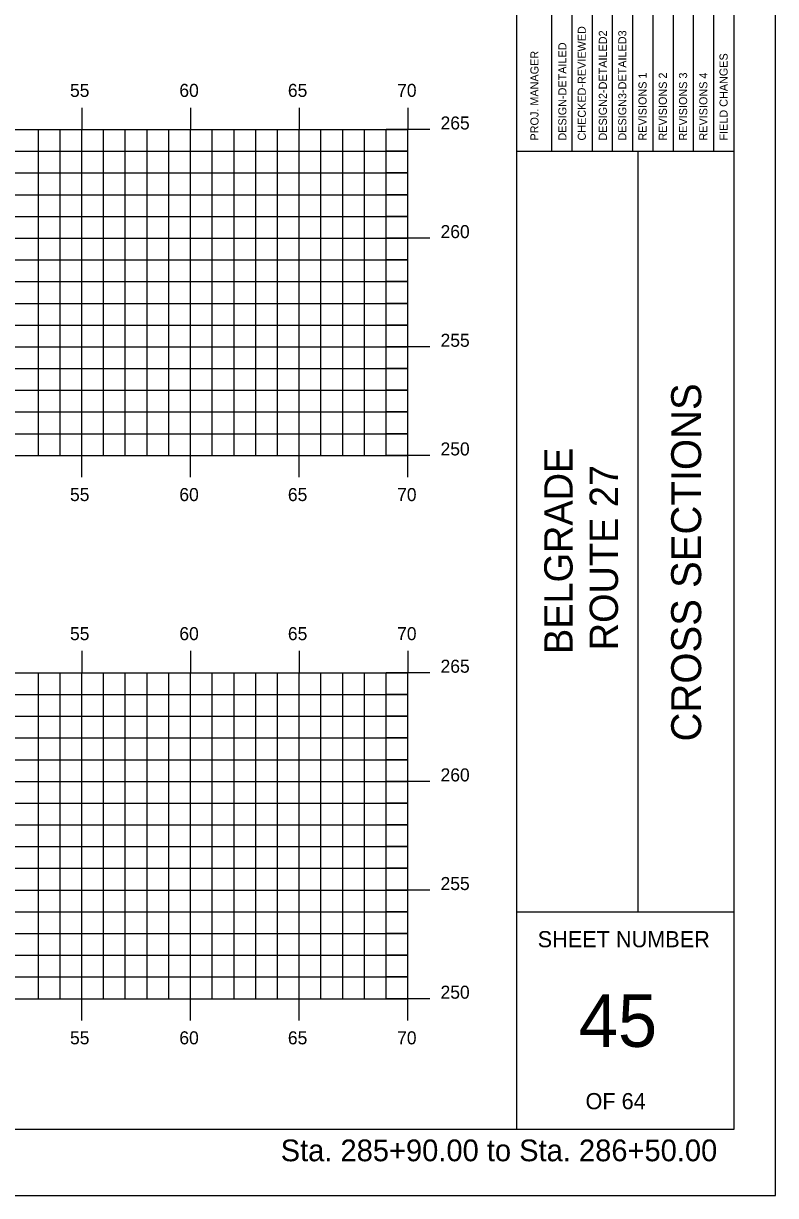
# Model space of a CAD drawing. Extents: x 856903 to 857073, y 366268 to 366378.
# Drawn here: x 857038.1 to 857072.7, y 366268.2 to 366322.1 of the extents above; entities that cross this region are included whole.
import ezdxf

# ---------------------------------------------------------------- set-up
doc = ezdxf.new("R2010")
doc.units = 0
for name, color, linetype in [('BORDER', 7, 'Continuous'), ('H_V ANNOTATION', 7, 'Continuous'), ('HIGHWAY_TITLE', 7, 'Continuous'), ('MAJOR', 7, 'Continuous'), ('MINOR', 7, 'Continuous'), ('PLOT BOUNDARY', 7, 'Continuous')]:
    doc.layers.add(name, color=color, linetype=linetype)

msp = doc.modelspace()

# ---------------------------------------------------------------- linework, layer by layer
at = {"layer": 'BORDER'}
for p, q in [((857060.784, 366271.236), (857060.784, 366376.239)), ((857070.784, 366271.236), (857070.784, 366376.236)), ((857060.784, 366316.239), (857070.784, 366316.239)), ((857066.375, 366281.239), (857066.375, 366316.239)), ((857060.784, 366281.239), (857070.784, 366281.239)), ((856910.784, 366271.236), (857070.784, 366271.236))]:
    msp.add_line(p, q, dxfattribs=at)
for points in [[(857063.332, 366316.242), (857063.332, 366333.739)], [(857064.263, 366333.739), (857064.263, 366316.242)], [(857065.195, 366316.242), (857065.195, 366333.739)], [(857066.127, 366316.242), (857066.127, 366333.739)], [(857067.058, 366316.242), (857067.058, 366333.739)], [(857067.99, 366316.242), (857067.99, 366333.739)], [(857068.922, 366316.242), (857068.922, 366333.739)], [(857069.853, 366316.242), (857069.853, 366333.739)], [(857062.4, 366316.242), (857062.4, 366333.033)]]:
    msp.add_lwpolyline(points, dxfattribs=at)
at = {"layer": 'MAJOR'}
for p, q in [((857040.784, 366318.238), (857040.784, 366317.236)), ((857045.784, 366318.238), (857045.784, 366317.236)), ((857050.784, 366318.238), (857050.784, 366317.236)), ((857055.784, 366318.238), (857055.784, 366317.236)), ((856915.784, 366317.236), (857055.784, 366317.236)), ((856915.784, 366317.236), (857055.784, 366317.236)), ((857040.784, 366302.236), (857040.784, 366317.236)), ((857045.784, 366302.236), (857045.784, 366317.236)), ((857050.784, 366302.236), (857050.784, 366317.236)), ((857056.786, 366317.236), (857054.782, 366317.236)), ((857055.784, 366302.236), (857055.784, 366317.236)), ((857055.784, 366302.236), (857055.784, 366317.236)), ((856915.784, 366312.236), (857055.784, 366312.236)), ((857056.786, 366312.236), (857054.782, 366312.236)), ((856915.784, 366307.236), (857055.784, 366307.236)), ((857056.786, 366307.236), (857054.782, 366307.236)), ((856915.784, 366302.236), (857055.784, 366302.236)), ((856915.784, 366302.236), (857055.784, 366302.236)), ((857040.784, 366301.234), (857040.784, 366302.236)), ((857045.784, 366301.234), (857045.784, 366302.236)), ((857050.784, 366301.234), (857050.784, 366302.236)), ((857056.786, 366302.236), (857054.782, 366302.236)), ((857055.784, 366301.234), (857055.784, 366302.236)), ((857040.784, 366293.238), (857040.784, 366292.236)), ((857045.784, 366293.238), (857045.784, 366292.236)), ((857050.784, 366293.238), (857050.784, 366292.236)), ((857055.784, 366293.238), (857055.784, 366292.236)), ((856915.784, 366292.236), (857055.784, 366292.236)), ((856915.784, 366292.236), (857055.784, 366292.236)), ((857040.784, 366277.236), (857040.784, 366292.236)), ((857045.784, 366277.236), (857045.784, 366292.236)), ((857050.784, 366277.236), (857050.784, 366292.236)), ((857056.786, 366292.236), (857054.782, 366292.236)), ((857055.784, 366277.236), (857055.784, 366292.236)), ((857055.784, 366277.236), (857055.784, 366292.236)), ((856915.784, 366287.236), (857055.784, 366287.236)), ((857056.786, 366287.236), (857054.782, 366287.236)), ((856915.784, 366282.236), (857055.784, 366282.236)), ((857056.786, 366282.236), (857054.782, 366282.236)), ((856915.784, 366277.236), (857055.784, 366277.236)), ((856915.784, 366277.236), (857055.784, 366277.236)), ((857040.784, 366276.234), (857040.784, 366277.236)), ((857045.784, 366276.234), (857045.784, 366277.236)), ((857050.784, 366276.234), (857050.784, 366277.236)), ((857056.786, 366277.236), (857054.782, 366277.236)), ((857055.784, 366276.234), (857055.784, 366277.236))]:
    msp.add_line(p, q, dxfattribs=at)
at = {"layer": 'MINOR'}
for p, q in [((857038.784, 366302.236), (857038.784, 366317.236)), ((857039.784, 366302.236), (857039.784, 366317.236)), ((857041.784, 366302.236), (857041.784, 366317.236)), ((857042.784, 366302.236), (857042.784, 366317.236)), ((857043.784, 366302.236), (857043.784, 366317.236)), ((857044.784, 366302.236), (857044.784, 366317.236)), ((857046.784, 366302.236), (857046.784, 366317.236)), ((857047.784, 366302.236), (857047.784, 366317.236)), ((857048.784, 366302.236), (857048.784, 366317.236)), ((857049.784, 366302.236), (857049.784, 366317.236)), ((857051.784, 366302.236), (857051.784, 366317.236)), ((857052.784, 366302.236), (857052.784, 366317.236)), ((857053.784, 366302.236), (857053.784, 366317.236)), ((857054.784, 366302.236), (857054.784, 366317.236)), ((856915.784, 366316.236), (857055.784, 366316.236)), ((857055.784, 366316.236), (857054.782, 366316.236)), ((856915.784, 366315.236), (857055.784, 366315.236)), ((857055.784, 366315.236), (857054.782, 366315.236)), ((856915.784, 366314.236), (857055.784, 366314.236)), ((857055.784, 366314.236), (857054.782, 366314.236)), ((856915.784, 366313.236), (857055.784, 366313.236)), ((857055.784, 366313.236), (857054.782, 366313.236)), ((856915.784, 366311.236), (857055.784, 366311.236)), ((857055.784, 366311.236), (857054.782, 366311.236)), ((856915.784, 366310.236), (857055.784, 366310.236)), ((857055.784, 366310.236), (857054.782, 366310.236)), ((856915.784, 366309.236), (857055.784, 366309.236)), ((857055.784, 366309.236), (857054.782, 366309.236)), ((856915.784, 366308.236), (857055.784, 366308.236)), ((857055.784, 366308.236), (857054.782, 366308.236)), ((856915.784, 366306.236), (857055.784, 366306.236)), ((857055.784, 366306.236), (857054.782, 366306.236)), ((856915.784, 366305.236), (857055.784, 366305.236)), ((857055.784, 366305.236), (857054.782, 366305.236)), ((856915.784, 366304.236), (857055.784, 366304.236)), ((857055.784, 366304.236), (857054.782, 366304.236)), ((856915.784, 366303.236), (857055.784, 366303.236)), ((857055.784, 366303.236), (857054.782, 366303.236)), ((857038.784, 366277.236), (857038.784, 366292.236)), ((857039.784, 366277.236), (857039.784, 366292.236)), ((857041.784, 366277.236), (857041.784, 366292.236)), ((857042.784, 366277.236), (857042.784, 366292.236)), ((857043.784, 366277.236), (857043.784, 366292.236)), ((857044.784, 366277.236), (857044.784, 366292.236)), ((857046.784, 366277.236), (857046.784, 366292.236)), ((857047.784, 366277.236), (857047.784, 366292.236)), ((857048.784, 366277.236), (857048.784, 366292.236)), ((857049.784, 366277.236), (857049.784, 366292.236)), ((857051.784, 366277.236), (857051.784, 366292.236)), ((857052.784, 366277.236), (857052.784, 366292.236)), ((857053.784, 366277.236), (857053.784, 366292.236)), ((857054.784, 366277.236), (857054.784, 366292.236)), ((856915.784, 366291.236), (857055.784, 366291.236)), ((857055.784, 366291.236), (857054.782, 366291.236)), ((856915.784, 366290.236), (857055.784, 366290.236)), ((857055.784, 366290.236), (857054.782, 366290.236)), ((856915.784, 366289.236), (857055.784, 366289.236)), ((857055.784, 366289.236), (857054.782, 366289.236)), ((856915.784, 366288.236), (857055.784, 366288.236)), ((857055.784, 366288.236), (857054.782, 366288.236)), ((856915.784, 366286.236), (857055.784, 366286.236)), ((857055.784, 366286.236), (857054.782, 366286.236)), ((856915.784, 366285.236), (857055.784, 366285.236)), ((857055.784, 366285.236), (857054.782, 366285.236)), ((856915.784, 366284.236), (857055.784, 366284.236)), ((857055.784, 366284.236), (857054.782, 366284.236)), ((856915.784, 366283.236), (857055.784, 366283.236)), ((857055.784, 366283.236), (857054.782, 366283.236)), ((856915.784, 366281.236), (857055.784, 366281.236)), ((857055.784, 366281.236), (857054.782, 366281.236)), ((856915.784, 366280.236), (857055.784, 366280.236)), ((857055.784, 366280.236), (857054.782, 366280.236)), ((856915.784, 366279.236), (857055.784, 366279.236)), ((857055.784, 366279.236), (857054.782, 366279.236)), ((856915.784, 366278.236), (857055.784, 366278.236)), ((857055.784, 366278.236), (857054.782, 366278.236))]:
    msp.add_line(p, q, dxfattribs=at)
at = {"layer": 'PLOT BOUNDARY'}
msp.add_lwpolyline([(856902.691, 366268.177), (857072.691, 366268.177), (857072.691, 366378.177), (856902.691, 366378.177)], close=True, dxfattribs=at)

# ---------------------------------------------------------------- texts
at = {"layer": 'BORDER'}
for s, height, rotation, p in [('CHECKED-REVIEWED', 0.37275, 90, (857063.965, 366316.727)), ('DESIGN2-DETAILED2', 0.37275, 90, (857064.934, 366316.727)), ('DESIGN3-DETAILED3', 0.37275, 90, (857065.829, 366316.727)), ('PROJ. MANAGER', 0.37275, 90, (857061.788, 366316.727)), ('DESIGN-DETAILED', 0.37275, 90, (857063.071, 366316.727)), ('FIELD CHANGES', 0.37275, 90, (857070.487, 366316.727)), ('REVISIONS 1', 0.37275, 90, (857066.76, 366316.727)), ('REVISIONS 2', 0.37275, 90, (857067.692, 366316.727)), ('REVISIONS 3', 0.37275, 90, (857068.624, 366316.727)), ('REVISIONS 4', 0.37275, 90, (857069.555, 366316.727)), ('CROSS SECTIONS', 1.37787, 90, (857069.269, 366289.073)), ('SHEET NUMBER', 0.74527, 360, (857061.75, 366279.603)), ('45', 2.4194, 360, (857063.645, 366275.019)), ('OF 64', 0.7453, 360, (857063.951, 366272.149))]:
    msp.add_text(s, height=height, rotation=rotation, dxfattribs=at).set_placement(p)
at = {"layer": 'H_V ANNOTATION'}
for s, height, p in [('55', 0.6, (857040.241, 366318.736)), ('60', 0.6, (857045.27, 366318.736)), ('65', 0.6, (857050.262, 366318.736)), ('70', 0.6, (857055.286, 366318.736)), ('265', 0.6, (857057.284, 366317.236)), ('260', 0.6, (857057.284, 366312.236)), ('255', 0.6, (857057.284, 366307.236)), ('250', 0.6, (857057.284, 366302.236)), ('55', 0.6, (857040.241, 366300.136)), ('60', 0.6, (857045.27, 366300.136)), ('65', 0.6, (857050.262, 366300.136)), ('70', 0.6, (857055.286, 366300.136)), ('55', 0.6, (857040.241, 366293.736)), ('60', 0.6, (857045.27, 366293.736)), ('65', 0.6, (857050.262, 366293.736)), ('70', 0.6, (857055.286, 366293.736)), ('265', 0.6, (857057.284, 366292.236)), ('260', 0.6, (857057.284, 366287.236)), ('255', 0.6, (857057.284, 366282.236)), ('250', 0.6, (857057.284, 366277.236)), ('55', 0.6, (857040.241, 366275.136)), ('60', 0.6, (857045.27, 366275.136)), ('65', 0.6, (857050.262, 366275.136)), ('70', 0.6, (857055.286, 366275.136)), ('Sta. 285+90.00 to Sta. 286+50.00', 1.0002, (857049.93, 366269.756))]:
    msp.add_text(s, height=height, dxfattribs=at).set_placement(p)
at = {"layer": 'HIGHWAY_TITLE'}
for s, p in [('BELGRADE', (857063.357, 366293.095)), ('ROUTE 27', (857065.444, 366293.269))]:
    msp.add_text(s, height=1.3043, rotation=90, dxfattribs=at).set_placement(p)

doc.saveas('drawing.dxf')
